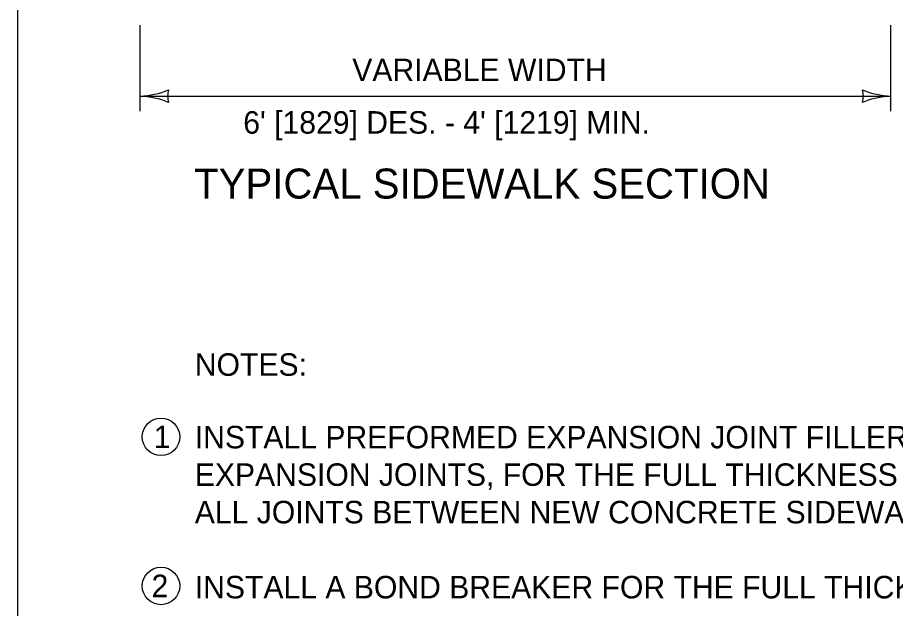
# Model space of a CAD drawing. Extents: x 49987.9 to 50021, y 49987.6 to 50011.4.
# Drawn here: x 50000.336 to 50002.674, y 50003.285 to 50004.86 of the extents above; entities that cross this region are included whole.
import ezdxf

# ---------------------------------------------------------------- set-up
doc = ezdxf.new("R2010")
doc.units = 0
for name, color, linetype in [('Level 1', 7, 'Continuous'), ('Level 2', 7, 'Continuous'), ('Level 3', 7, 'Continuous')]:
    doc.layers.add(name, color=color, linetype=linetype)

msp = doc.modelspace()

# ---------------------------------------------------------------- linework, layer by layer
at = {"layer": 'Level 1'}
msp.add_lwpolyline([(50008.6146, 50011.2628), (50000.3356, 50011.2628), (50000.3356, 50000.0624), (50008.6146, 50000.0624)], close=True, dxfattribs=at)
at = {"layer": 'Level 2'}
for centre in [(50000.7177, 50003.7421), (50000.7177, 50003.3447)]:
    msp.add_circle(centre, 0.05, dxfattribs=at)
at = {"layer": 'Level 3'}
for p, q in [((50000.6619, 50004.6104), (50000.6619, 50004.84)), ((50002.6619, 50004.6104), (50002.6619, 50004.84)), ((50000.6619, 50004.6504), (50002.6619, 50004.6504))]:
    msp.add_line(p, q, dxfattribs=at)
for centre, radius, start, end in [((50000.6504, 50004.8831), 0.233, 272.8273, 292.0772), ((50000.7901, 50004.6504), 0.0548, 162.1388, 197.8612), ((50002.6711, 50004.8725), 0.2223, 247.456, 267.6395), ((50002.5337, 50004.6504), 0.0548, 342.1388, 17.8612), ((50000.6528, 50004.4282), 0.2223, 67.456, 87.6395), ((50002.6734, 50004.4177), 0.233, 92.8273, 112.0772)]:
    msp.add_arc(centre, radius, start, end, dxfattribs=at)

# ---------------------------------------------------------------- texts
at = {"layer": 'Level 2'}
for s, height, p in [('VARIABLE WIDTH', 0.06, (50001.2272, 50004.6904)), ("6' [1829] DES. - 4' [1219] MIN.", 0.06, (50000.9368, 50004.5504)), ('TYPICAL SIDEWALK SECTION', 0.08, (50000.806, 50004.3774)), ('NOTES:', 0.06, (50000.8077, 50003.9049)), ('1', 0.06, (50000.6982, 50003.7121)), ('INSTALL PREFORMED EXPANSION JOINT FILLER, PER SECTION 707, AT ALL', 0.06, (50000.8077, 50003.7115)), ('EXPANSION JOINTS, FOR THE FULL THICKNESS OF THE SIDEWALK AND USE AT', 0.06, (50000.8077, 50003.6115)), ('ALL JOINTS BETWEEN NEW CONCRETE SIDEWALK AND STRUCTURES IN PLACE.', 0.06, (50000.8077, 50003.5115)), ('2', 0.06, (50000.6926, 50003.3147)), ('INSTALL A BOND BREAKER FOR THE FULL THICKNESS OF THE SIDEWALK AT', 0.06, (50000.8077, 50003.3115))]:
    msp.add_text(s, height=height, dxfattribs=at).set_placement(p)

doc.saveas('drawing.dxf')
